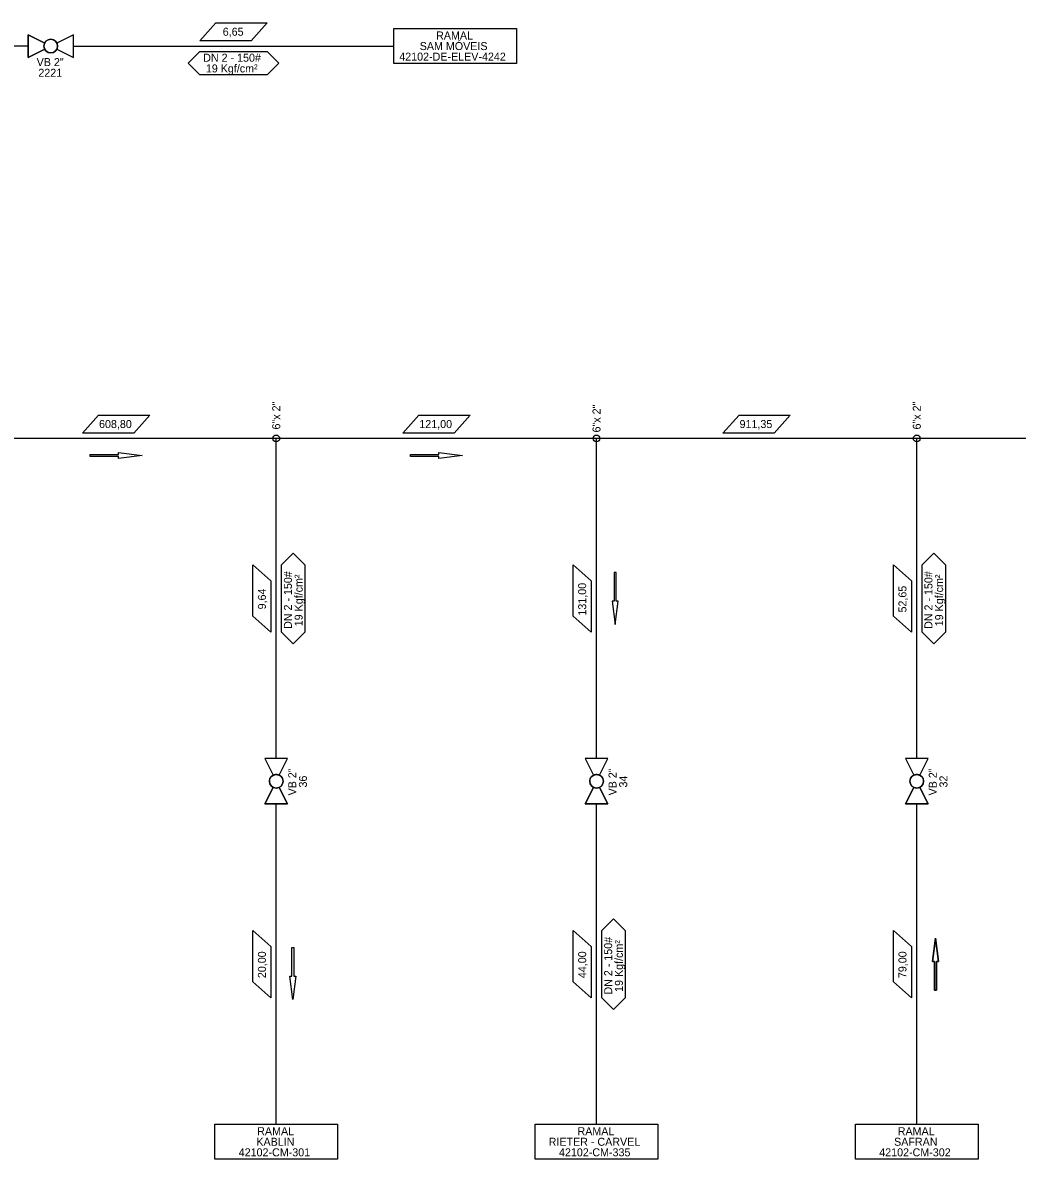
# Model space of a CAD drawing. Extents: x -39999 to 23586, y -25927 to 32541.
# Drawn here: x -38435.3 to -38062.6, y -262.2 to 163.7 of the extents above; entities that cross this region are included whole.
import ezdxf

# ---------------------------------------------------------------- set-up
doc = ezdxf.new("R2010")
doc.units = 0
for name, color, linetype in [('LEGENDA', 7, 'Continuous'), ('SIMBOLO', 7, 'Continuous'), ('TEXTO', 7, 'Continuous'), ('TUBO_ACO_GN_2', 7, 'Continuous'), ('TUBO_ACO_GN_6', 7, 'Continuous'), ('VALVULA_ACO_2', 7, 'Continuous')]:
    doc.layers.add(name, color=color, linetype=linetype)

# ---------------------------------------------------------------- blocks, each defined once
blk = doc.blocks.new('VALVULA_ACO_2')
at = {"layer": 'VALVULA_ACO_2'}
for points in [[(-1.14, 0.57), (-4.25, 2.13), (-4.25, -2.13), (-1.14, -0.57)], [(-1.14, -0.57), (-4.25, -2.13), (-4.25, 2.13), (-1.14, 0.57)], [(1.14, -0.57), (4.25, -2.13), (4.25, 2.13), (1.14, 0.57)], [(1.14, -0.57), (4.25, -2.13), (4.25, 2.13), (1.14, 0.57)]]:
    blk.add_lwpolyline(points, dxfattribs=at)
blk.add_circle((0, 0), 1.28, dxfattribs=at)
for start, end in [(90, 270), (153.4349, 206.5651), (270, 90), (0, 26.5651), (333.4349, 0)]:
    blk.add_arc((0, 0), 1.28, start, end, dxfattribs=at)

msp = doc.modelspace()

# ---------------------------------------------------------------- linework, layer by layer
at = {"layer": 'LEGENDA'}
for points in [[(-38399.32, 0.42), (-38399.32, 1.17), (-38410.01, 1.17), (-38410.01, 1.92), (-38399.32, 1.92), (-38399.32, 2.67), (-38390.52, 1.54)], [(-38399.32, 0.42), (-38399.32, 1.17), (-38410.01, 1.17), (-38410.01, 1.92), (-38399.32, 1.92), (-38399.32, 2.67), (-38390.52, 1.54)], [(-38279.32, 0.42), (-38279.32, 1.17), (-38290.01, 1.17), (-38290.01, 1.92), (-38279.32, 1.92), (-38279.32, 2.67), (-38270.52, 1.54)], [(-38279.32, 0.42), (-38279.32, 1.17), (-38290.01, 1.17), (-38290.01, 1.92), (-38279.32, 1.92), (-38279.32, 2.67), (-38270.52, 1.54)], [(-38213.27, -61.83), (-38212.14, -53.03), (-38212.89, -53.03), (-38212.89, -42.34), (-38213.64, -42.34), (-38213.64, -53.03), (-38214.39, -53.03)], [(-38212.14, -53.03), (-38212.89, -53.03), (-38212.89, -42.34), (-38213.64, -42.34), (-38213.64, -53.03), (-38214.39, -53.03), (-38213.27, -61.83)], [(-38334.02, -202.4), (-38335.14, -193.6), (-38334.39, -193.6), (-38334.39, -182.91), (-38333.64, -182.91), (-38333.64, -193.6), (-38332.89, -193.6)], [(-38335.14, -193.6), (-38334.39, -193.6), (-38334.39, -182.91), (-38333.64, -182.91), (-38333.64, -193.6), (-38332.89, -193.6), (-38334.02, -202.4)], [(-38092.89, -198.84), (-38092.89, -188.15), (-38092.14, -188.15), (-38093.27, -179.35), (-38094.39, -188.15), (-38093.64, -188.15), (-38093.64, -198.84)], [(-38092.14, -188.15), (-38092.89, -188.15), (-38092.89, -198.84), (-38093.64, -198.84), (-38093.64, -188.15), (-38094.39, -188.15), (-38093.27, -179.35)]]:
    msp.add_lwpolyline(points, close=True, dxfattribs=at)
at = {"layer": 'SIMBOLO'}
for points in [[(-38349.63, 156.93), (-38368.85, 156.93), (-38362.85, 163.68), (-38343.63, 163.68)], [(-38296.24, 161.49), (-38250.24, 161.49), (-38250.24, 148.36), (-38296.24, 148.36)], [(-38393.66, 9.91), (-38412.88, 9.91), (-38406.88, 16.66), (-38387.66, 16.66)], [(-38273.66, 9.91), (-38292.88, 9.91), (-38286.88, 16.66), (-38267.66, 16.66)], [(-38153.66, 9.91), (-38172.88, 9.91), (-38166.88, 16.66), (-38147.66, 16.66)], [(-38342.27, -45.48), (-38342.27, -64.69), (-38349.02, -58.69), (-38349.02, -39.48)], [(-38222.27, -45.48), (-38222.27, -64.69), (-38229.02, -58.69), (-38229.02, -39.48)], [(-38102.27, -45.48), (-38102.27, -64.69), (-38109.02, -58.69), (-38109.02, -39.48)], [(-38342.27, -182.49), (-38342.27, -201.71), (-38349.02, -195.71), (-38349.02, -176.49)], [(-38222.27, -182.49), (-38222.27, -201.71), (-38229.02, -195.71), (-38229.02, -176.49)], [(-38102.27, -182.49), (-38102.27, -201.71), (-38109.02, -195.71), (-38109.02, -176.49)], [(-38363.27, -249.1), (-38317.27, -249.1), (-38317.27, -262.22), (-38363.27, -262.22)], [(-38243.27, -249.1), (-38197.27, -249.1), (-38197.27, -262.22), (-38243.27, -262.22)], [(-38123.27, -249.1), (-38077.27, -249.1), (-38077.27, -262.22), (-38123.27, -262.22)]]:
    msp.add_lwpolyline(points, close=True, dxfattribs=at)
for points in [[(-38339.24, 148.55), (-38343.62, 144.18), (-38368.87, 144.18), (-38373.24, 148.55), (-38368.87, 152.93), (-38343.62, 152.93), (-38339.24, 148.55)], [(-38333.89, -35.09), (-38329.52, -39.46), (-38329.52, -64.71), (-38333.89, -69.09), (-38338.27, -64.71), (-38338.27, -39.46), (-38333.89, -35.09)], [(-38093.89, -35.09), (-38089.52, -39.46), (-38089.52, -64.71), (-38093.89, -69.09), (-38098.27, -64.71), (-38098.27, -39.46), (-38093.89, -35.09)], [(-38213.89, -172.1), (-38209.52, -176.47), (-38209.52, -201.72), (-38213.89, -206.1), (-38218.27, -201.72), (-38218.27, -176.47), (-38213.89, -172.1)]]:
    msp.add_lwpolyline(points, dxfattribs=at)
for centre in [(-38340.27, 7.91), (-38220.27, 7.91), (-38100.27, 7.91)]:
    msp.add_circle(centre, 1.27, dxfattribs=at)
at = {"layer": 'TUBO_ACO_GN_2'}
for p, q in [((-38433.25, 154.93), (-38673.25, 154.93)), ((-38416.24, 154.93), (-38296.24, 154.93)), ((-38340.27, -112.09), (-38340.27, 7.91)), ((-38220.27, -112.09), (-38220.27, 7.91)), ((-38100.27, -112.09), (-38100.27, 7.91)), ((-38340.27, -249.1), (-38340.27, -129.1)), ((-38220.27, -249.1), (-38220.27, -129.1)), ((-38100.27, -249.1), (-38100.27, -129.1))]:
    msp.add_line(p, q, dxfattribs=at)
at = {"layer": 'TUBO_ACO_GN_6'}
msp.add_line((-37980.27, 7.91), (-39420.27, 7.91), dxfattribs=at)

# ---------------------------------------------------------------- block references
at = {"layer": 'VALVULA_ACO_2', "xscale": 2, "yscale": 2}
msp.add_blockref('VALVULA_ACO_2', (-38424.75, 154.93), dxfattribs=at)
at = {"layer": 'VALVULA_ACO_2', "xscale": 2, "yscale": 2, "rotation": 89.99999999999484}
for p in [(-38340.27, -120.59), (-38220.27, -120.59), (-38100.27, -120.59)]:
    msp.add_blockref('VALVULA_ACO_2', p, dxfattribs=at)

# ---------------------------------------------------------------- texts
for s, p in [('VB 2"', (-38430.04, 147.43)), ('2221', (-38429.41, 143.43))]:
    msp.add_text(s, height=3).set_placement(p)
for s, p in [('VB 2"', (-38332.77, -125.88)), ('36', (-38328.77, -122.92)), ('VB 2"', (-38212.77, -125.88)), ('34', (-38208.77, -122.92)), ('VB 2"', (-38092.77, -125.88)), ('32', (-38088.77, -122.92))]:
    msp.add_text(s, height=3, rotation=90).set_placement(p)
at = {"layer": 'TEXTO'}
for s, p in [('6,65', (-38360.32, 158.8)), ('RAMAL', (-38280.38, 157.39)), ('SAM MÓVEIS', (-38286.52, 153.43)), ('DN 2 - 150#', (-38367.65, 149.06)), ('42102-DE-ELEV-4242', (-38294.18, 149.47)), ('19 Kgf/cm²', (-38366.64, 145.05)), ('608,80', (-38406.67, 11.79)), ('121,00', (-38286.67, 11.79)), ('911,35', (-38166.67, 11.79)), ('RAMAL', (-38347.4, -253.2)), ('RAMAL', (-38227.4, -253.2)), ('RAMAL', (-38107.4, -253.2)), ('KABLIN', (-38347.72, -257.16)), ('RIETER - CARVEL', (-38238.2, -257.16)), ('SAFRAN', (-38108.77, -257.16)), ('42102-CM-301', (-38354.33, -261.12)), ('42102-CM-335', (-38234.33, -261.12)), ('42102-CM-302', (-38114.33, -261.12))]:
    msp.add_text(s, height=3, dxfattribs=at).set_placement(p)
for s, p in [('   6"x 2"  ', (-38338.77, 7.91)), ('   6"x 2"', (-38098.77, 7.91)), ('  6"x 2"', (-38218.77, 7.91)), ('DN 2 - 150#', (-38334.4, -63.49)), ('DN 2 - 150#', (-38094.4, -63.49)), ('19 Kgf/cm²', (-38330.39, -62.49)), ('131,00', (-38224.14, -58.49)), ('19 Kgf/cm²', (-38090.39, -62.49)), ('9,64', (-38344.14, -56.16)), ('52,65', (-38104.14, -57.33)), ('DN 2 - 150#', (-38214.4, -200.5)), ('19 Kgf/cm²', (-38210.39, -199.5)), ('20,00', (-38344.14, -194.34)), ('44,00', (-38224.14, -194.34)), ('79,00', (-38104.14, -194.34))]:
    msp.add_text(s, height=3, rotation=90, dxfattribs=at).set_placement(p)

doc.saveas('drawing.dxf')
